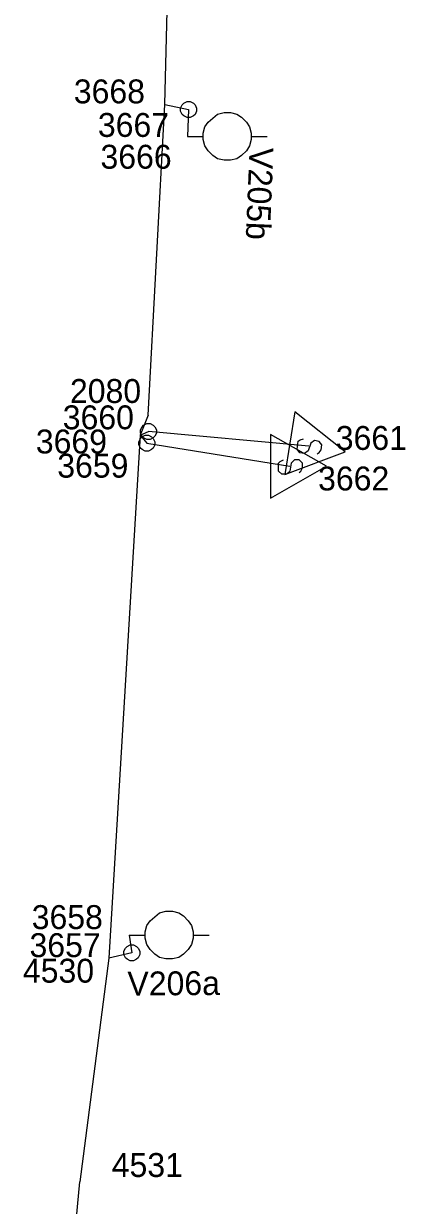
# Model space of a CAD drawing. Extents: x -535557 to -534097, y -1142175 to -1136716.
# Drawn here: x -534433.78 to -534421.81, y -1139812.57 to -1139775.49 of the extents above; entities that cross this region are included whole.
import ezdxf

# ---------------------------------------------------------------- set-up
doc = ezdxf.new("R2010")
doc.units = 0
doc.layers.add('Default', color=7, linetype='Continuous')
doc.layers.add('SS_SZDC', color=7, linetype='Continuous')

# ---------------------------------------------------------------- blocks, each defined once
blk = doc.blocks.new('POINT_DISPLAY')
at = {"layer": 'Default'}
blk.add_line((0, 0), (0, 0), dxfattribs=at)

msp = doc.modelspace()

# ---------------------------------------------------------------- linework, layer by layer
at = {"layer": 'SS_SZDC'}
for p, q in [((-534429.359, -1139778.03), (-534429.14, -1139769.28)), ((-534429.88, -1139787.78), (-534429.359, -1139778.03)), ((-534429.359, -1139778.03), (-534428.609, -1139778.19)), ((-534428.859, -1139778.14), (-534428.809, -1139778.04)), ((-534428.859, -1139778.24), (-534428.859, -1139778.14)), ((-534428.809, -1139778.04), (-534428.759, -1139777.99)), ((-534428.759, -1139777.99), (-534428.659, -1139777.94)), ((-534428.659, -1139777.94), (-534428.559, -1139777.94)), ((-534428.609, -1139778.19), (-534428.649, -1139779.03)), ((-534428.559, -1139777.94), (-534428.459, -1139777.99)), ((-534428.459, -1139777.99), (-534428.409, -1139778.04)), ((-534428.409, -1139778.04), (-534428.359, -1139778.14)), ((-534428.359, -1139778.14), (-534428.359, -1139778.24)), ((-534428.809, -1139778.34), (-534428.859, -1139778.24)), ((-534428.759, -1139778.39), (-534428.809, -1139778.34)), ((-534428.659, -1139778.44), (-534428.759, -1139778.39)), ((-534428.559, -1139778.44), (-534428.659, -1139778.44)), ((-534428.459, -1139778.39), (-534428.559, -1139778.44)), ((-534428.409, -1139778.34), (-534428.459, -1139778.39)), ((-534428.359, -1139778.24), (-534428.409, -1139778.34)), ((-534428.099, -1139778.73), (-534427.999, -1139778.58)), ((-534427.999, -1139778.58), (-534427.699, -1139778.33)), ((-534427.699, -1139778.33), (-534427.499, -1139778.28)), ((-534427.499, -1139778.28), (-534427.299, -1139778.28)), ((-534427.299, -1139778.28), (-534427.099, -1139778.33)), ((-534427.099, -1139778.33), (-534426.949, -1139778.43)), ((-534426.949, -1139778.43), (-534426.799, -1139778.58)), ((-534426.799, -1139778.58), (-534426.699, -1139778.73)), ((-534428.149, -1139778.93), (-534428.099, -1139778.73)), ((-534428.149, -1139779.03), (-534428.149, -1139778.93)), ((-534426.699, -1139778.73), (-534426.649, -1139778.93)), ((-534426.649, -1139778.93), (-534426.649, -1139779.13)), ((-534428.649, -1139779.03), (-534428.149, -1139779.03)), ((-534428.149, -1139779.13), (-534428.149, -1139779.03)), ((-534428.099, -1139779.33), (-534428.149, -1139779.13)), ((-534426.649, -1139779.13), (-534426.699, -1139779.33)), ((-534426.649, -1139779.03), (-534426.149, -1139779.03)), ((-534427.999, -1139779.48), (-534428.099, -1139779.33)), ((-534427.849, -1139779.63), (-534427.999, -1139779.48)), ((-534427.699, -1139779.73), (-534427.849, -1139779.63)), ((-534426.949, -1139779.63), (-534427.099, -1139779.73)), ((-534426.799, -1139779.48), (-534426.949, -1139779.63)), ((-534426.699, -1139779.33), (-534426.799, -1139779.48)), ((-534427.499, -1139779.78), (-534427.699, -1139779.73)), ((-534427.299, -1139779.78), (-534427.499, -1139779.78)), ((-534427.099, -1139779.73), (-534427.299, -1139779.78)), ((-534429.88, -1139787.78), (-534430.13, -1139788.409)), ((-534425.276, -1139787.668), (-534425.589, -1139789.643)), ((-534423.704, -1139788.929), (-534425.276, -1139787.668)), ((-534430.119, -1139788.24), (-534430.069, -1139788.14)), ((-534430.069, -1139788.14), (-534430.019, -1139788.09)), ((-534430.019, -1139788.09), (-534429.919, -1139788.04)), ((-534429.919, -1139788.04), (-534429.819, -1139788.04)), ((-534429.819, -1139788.04), (-534429.719, -1139788.09)), ((-534429.719, -1139788.09), (-534429.669, -1139788.14)), ((-534429.669, -1139788.14), (-534429.619, -1139788.24)), ((-534430.13, -1139788.409), (-534431.109, -1139804.809)), ((-534430.17, -1139788.609), (-534430.12, -1139788.509)), ((-534430.13, -1139788.409), (-534429.869, -1139788.29)), ((-534430.13, -1139788.409), (-534429.92, -1139788.659)), ((-534430.12, -1139788.509), (-534430.07, -1139788.459)), ((-534430.119, -1139788.34), (-534430.119, -1139788.24)), ((-534430.069, -1139788.44), (-534430.119, -1139788.34)), ((-534430.07, -1139788.459), (-534429.97, -1139788.409)), ((-534430.019, -1139788.49), (-534430.069, -1139788.44)), ((-534429.919, -1139788.54), (-534430.019, -1139788.49)), ((-534429.97, -1139788.409), (-534429.87, -1139788.409)), ((-534429.819, -1139788.54), (-534429.919, -1139788.54)), ((-534429.87, -1139788.409), (-534429.77, -1139788.459)), ((-534424.84, -1139788.75), (-534429.869, -1139788.29)), ((-534429.719, -1139788.49), (-534429.819, -1139788.54)), ((-534429.77, -1139788.459), (-534429.72, -1139788.509)), ((-534429.72, -1139788.509), (-534429.67, -1139788.609)), ((-534429.669, -1139788.44), (-534429.719, -1139788.49)), ((-534429.619, -1139788.34), (-534429.669, -1139788.44)), ((-534429.619, -1139788.24), (-534429.619, -1139788.34)), ((-534426.039, -1139788.379), (-534426.039, -1139790.379)), ((-534424.289, -1139789.379), (-534426.039, -1139788.379)), ((-534425.209, -1139788.843), (-534425.17, -1139788.596)), ((-534425.17, -1139788.596), (-534425.112, -1139788.554)), ((-534425.112, -1139788.554), (-534425.006, -1139788.521)), ((-534424.66, -1139788.575), (-534424.774, -1139788.659)), ((-534424.512, -1139788.599), (-534424.66, -1139788.575)), ((-534430.17, -1139788.709), (-534430.17, -1139788.609)), ((-534430.12, -1139788.809), (-534430.17, -1139788.709)), ((-534430.07, -1139788.859), (-534430.12, -1139788.809)), ((-534429.97, -1139788.909), (-534430.07, -1139788.859)), ((-534429.87, -1139788.909), (-534429.97, -1139788.909)), ((-534429.92, -1139788.659), (-534425.439, -1139789.379)), ((-534429.77, -1139788.859), (-534429.87, -1139788.909)), ((-534429.72, -1139788.809), (-534429.77, -1139788.859)), ((-534429.67, -1139788.709), (-534429.72, -1139788.809)), ((-534429.67, -1139788.609), (-534429.67, -1139788.709)), ((-534425.589, -1139789.643), (-534423.704, -1139788.929)), ((-534425.126, -1139788.957), (-534425.209, -1139788.843)), ((-534424.977, -1139788.981), (-534425.126, -1139788.957)), ((-534424.863, -1139788.898), (-534424.977, -1139788.981)), ((-534424.774, -1139788.659), (-534424.863, -1139788.898)), ((-534424.574, -1139788.994), (-534424.517, -1139788.952)), ((-534424.517, -1139788.952), (-534424.452, -1139788.861)), ((-534424.429, -1139788.713), (-534424.512, -1139788.599)), ((-534424.452, -1139788.861), (-534424.429, -1139788.713)), ((-534425.789, -1139789.279), (-534425.739, -1139789.229)), ((-534425.789, -1139789.529), (-534425.789, -1139789.279)), ((-534425.739, -1139789.229), (-534425.639, -1139789.179)), ((-534425.389, -1139789.279), (-534425.439, -1139789.529)), ((-534425.289, -1139789.179), (-534425.389, -1139789.279)), ((-534425.139, -1139789.179), (-534425.289, -1139789.179)), ((-534425.039, -1139789.279), (-534425.139, -1139789.179)), ((-534425.039, -1139789.429), (-534425.039, -1139789.279)), ((-534426.039, -1139790.379), (-534424.289, -1139789.379)), ((-534425.689, -1139789.629), (-534425.789, -1139789.529)), ((-534425.539, -1139789.629), (-534425.689, -1139789.629)), ((-534425.439, -1139789.529), (-534425.539, -1139789.629)), ((-534425.139, -1139789.579), (-534425.089, -1139789.529)), ((-534425.089, -1139789.529), (-534425.039, -1139789.429)), ((-534429.82, -1139803.64), (-534429.52, -1139803.39)), ((-534429.52, -1139803.39), (-534429.32, -1139803.34)), ((-534429.32, -1139803.34), (-534429.12, -1139803.34)), ((-534429.12, -1139803.34), (-534428.92, -1139803.39)), ((-534428.92, -1139803.39), (-534428.77, -1139803.49)), ((-534429.97, -1139803.99), (-534429.92, -1139803.79)), ((-534429.92, -1139803.79), (-534429.82, -1139803.64)), ((-534428.77, -1139803.49), (-534428.62, -1139803.64)), ((-534428.62, -1139803.64), (-534428.52, -1139803.79)), ((-534428.52, -1139803.79), (-534428.47, -1139803.99)), ((-534430.47, -1139804.09), (-534430.39, -1139804.649)), ((-534430.47, -1139804.09), (-534429.97, -1139804.09)), ((-534429.97, -1139804.09), (-534429.97, -1139803.99)), ((-534429.97, -1139804.19), (-534429.97, -1139804.09)), ((-534428.47, -1139803.99), (-534428.47, -1139804.19)), ((-534428.47, -1139804.09), (-534427.97, -1139804.09)), ((-534430.64, -1139804.599), (-534430.59, -1139804.499)), ((-534430.59, -1139804.499), (-534430.54, -1139804.449)), ((-534430.54, -1139804.449), (-534430.44, -1139804.399)), ((-534430.44, -1139804.399), (-534430.34, -1139804.399)), ((-534430.34, -1139804.399), (-534430.24, -1139804.449)), ((-534430.24, -1139804.449), (-534430.19, -1139804.499)), ((-534430.19, -1139804.499), (-534430.14, -1139804.599)), ((-534429.92, -1139804.39), (-534429.97, -1139804.19)), ((-534429.82, -1139804.54), (-534429.92, -1139804.39)), ((-534429.67, -1139804.69), (-534429.82, -1139804.54)), ((-534428.62, -1139804.54), (-534428.77, -1139804.69)), ((-534428.52, -1139804.39), (-534428.62, -1139804.54)), ((-534428.47, -1139804.19), (-534428.52, -1139804.39)), ((-534431.109, -1139804.809), (-534432.02, -1139811.829)), ((-534430.39, -1139804.649), (-534431.109, -1139804.809)), ((-534430.64, -1139804.699), (-534430.64, -1139804.599)), ((-534430.59, -1139804.799), (-534430.64, -1139804.699)), ((-534430.54, -1139804.849), (-534430.59, -1139804.799)), ((-534430.44, -1139804.899), (-534430.54, -1139804.849)), ((-534430.34, -1139804.899), (-534430.44, -1139804.899)), ((-534430.24, -1139804.849), (-534430.34, -1139804.899)), ((-534430.19, -1139804.799), (-534430.24, -1139804.849)), ((-534430.14, -1139804.699), (-534430.19, -1139804.799)), ((-534430.14, -1139804.599), (-534430.14, -1139804.699)), ((-534429.52, -1139804.79), (-534429.67, -1139804.69)), ((-534429.32, -1139804.84), (-534429.52, -1139804.79)), ((-534429.12, -1139804.84), (-534429.32, -1139804.84)), ((-534428.92, -1139804.79), (-534429.12, -1139804.84)), ((-534428.77, -1139804.69), (-534428.92, -1139804.79)), ((-534432.319, -1139814.969), (-534432.02, -1139811.829))]:
    msp.add_line(p, q, dxfattribs=at)

# ---------------------------------------------------------------- block references
for p in [(-534429.359, -1139778.03), (-534428.609, -1139778.19), (-534428.609, -1139778.19), (-534428.649, -1139779.03), (-534429.88, -1139787.78), (-534430.13, -1139788.409), (-534429.869, -1139788.29), (-534429.869, -1139788.29), (-534429.92, -1139788.659), (-534429.92, -1139788.659), (-534424.84, -1139788.75), (-534425.439, -1139789.379), (-534430.47, -1139804.09), (-534431.109, -1139804.809), (-534430.39, -1139804.649), (-534430.39, -1139804.649), (-534432.02, -1139811.829)]:
    msp.add_blockref('POINT_DISPLAY', p, dxfattribs=at)

# ---------------------------------------------------------------- texts
for s, p in [('3668', (-534432.209, -1139777.994)), ('3667', (-534431.454, -1139779.046)), ('3666', (-534431.373, -1139780.044)), ('2080', (-534432.33, -1139787.394)), ('3660', (-534432.556, -1139788.22)), ('3669', (-534433.4, -1139788.978)), ('3661', (-534423.996, -1139788.867)), ('3659', (-534432.728, -1139789.737)), ('3662', (-534424.55, -1139790.139)), ('3658', (-534433.529, -1139803.901)), ('3657', (-534433.598, -1139804.781)), ('4530', (-534433.805, -1139805.583)), ('4531', (-534431.02, -1139811.679))]:
    msp.add_text(s, height=0.75, dxfattribs=at).set_placement(p)
for s, rotation, p in [('V205b', 267.6757, (-534426.698, -1139779.364)), ('V206a', 0.3757, (-534430.525, -1139805.988))]:
    msp.add_text(s, height=0.75, rotation=rotation, dxfattribs=at).set_placement(p)

doc.saveas('drawing.dxf')
